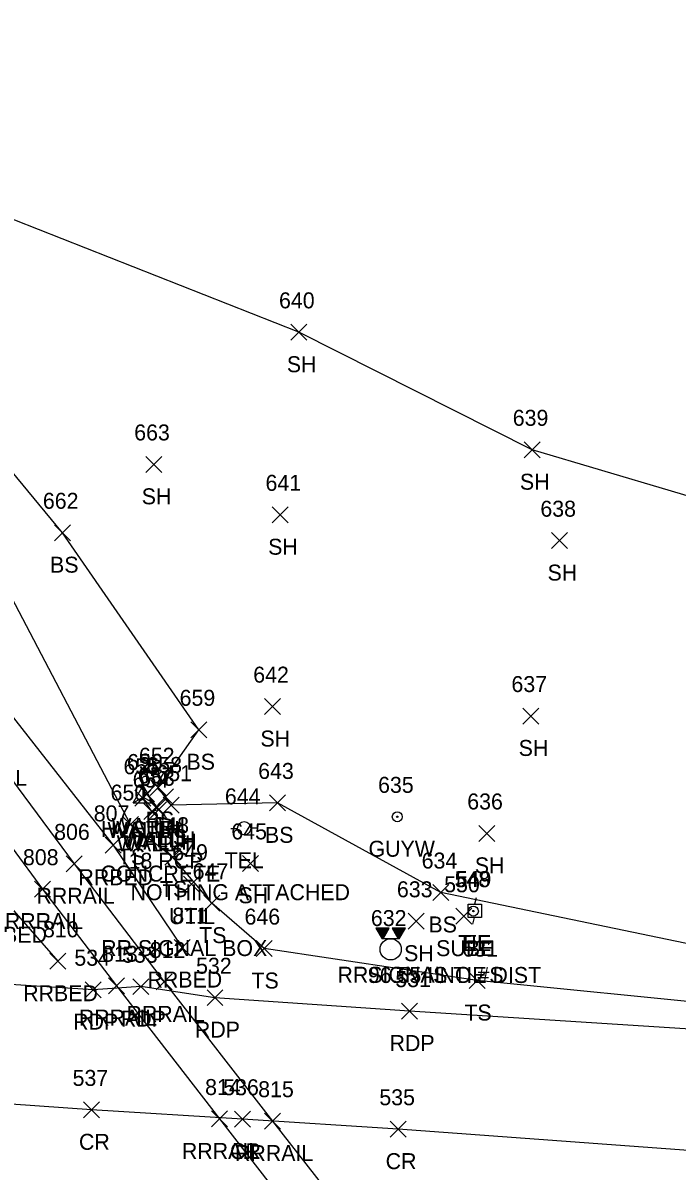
# Model space of a CAD drawing. Extents: x 1679360 to 1685861, y 903420 to 905946.
# Drawn here: x 1679800 to 1679882, y 904022.2 to 904166 of the extents above; entities that cross this region are included whole.
import ezdxf

# ---------------------------------------------------------------- set-up
doc = ezdxf.new("R2010")
doc.units = 0
for name, color, linetype in [('C_A', 7, 'Continuous'), ('C_C', 7, 'Continuous'), ('C_I', 7, 'Continuous'), ('CBP', 7, 'Continuous'), ('CPSM', 7, 'Continuous'), ('D_A', 7, 'Continuous'), ('D_C', 7, 'Continuous'), ('D_I', 7, 'Continuous'), ('D_TIC', 7, 'Continuous'), ('DHW', 7, 'Continuous'), ('L_A', 7, 'Continuous'), ('L_I', 7, 'Continuous'), ('L_TIC', 7, 'Continuous'), ('LELB', 7, 'Continuous'), ('LSOGP', 7, 'Continuous'), ('P_A', 7, 'Continuous'), ('P_I', 7, 'Continuous'), ('P_TIC', 7, 'Continuous'), ('PET', 7, 'Continuous'), ('PRC', 7, 'Continuous'), ('R_A', 7, 'Continuous'), ('R_I', 7, 'Continuous'), ('R_TIC', 7, 'Continuous'), ('RR', 7, 'Continuous'), ('RRB', 7, 'Continuous'), ('TCSH', 7, 'Continuous'), ('U_A', 7, 'Continuous'), ('U_C', 7, 'Continuous'), ('U_I', 7, 'Continuous'), ('U_TIC', 7, 'Continuous'), ('UDEFAULT', 7, 'Continuous'), ('UEPT', 7, 'Continuous'), ('UP', 7, 'Continuous'), ('UPGW', 7, 'Continuous')]:
    doc.layers.add(name, color=color, linetype=linetype)

msp = doc.modelspace()

# ---------------------------------------------------------------- linework, layer by layer
at = {"layer": 'CBP'}
for radius in [0.625, 0.0833]:
    msp.add_circle((1679856.45, 904054.75), radius, dxfattribs=at)
at = {"layer": 'CPSM'}
for p, q in [((1679813.83, 904068.31), (1679815.08, 904070.48)), ((1679816.33, 904068.31), (1679815.08, 904070.48)), ((1679815.08, 904069.03), (1679815.08, 904070.48)), ((1679813.83, 904068.31), (1679815.08, 904069.03)), ((1679815.08, 904069.03), (1679815.08, 904069.03)), ((1679815.08, 904069.03), (1679816.33, 904068.31)), ((1679813.83, 904068.31), (1679816.33, 904068.31))]:
    msp.add_line(p, q, dxfattribs=at)
at = {"layer": 'D_TIC'}
for points in [[(1679814.52, 904068.42), (1679816.52, 904070.42)], [(1679816.52, 904068.42), (1679814.52, 904070.42)], [(1679814.03, 904067.89), (1679816.03, 904069.89)], [(1679816.03, 904067.89), (1679814.03, 904069.89)], [(1679816.9, 904068.05), (1679818.9, 904070.05)], [(1679818.9, 904068.05), (1679816.9, 904070.05)], [(1679815.18, 904066.22), (1679817.18, 904068.22)], [(1679817.18, 904066.22), (1679815.18, 904068.22)], [(1679815.83, 904066.74), (1679817.83, 904068.74)], [(1679817.83, 904066.74), (1679815.83, 904068.74)], [(1679815.99, 904066.45), (1679817.99, 904068.45)], [(1679817.99, 904066.45), (1679815.99, 904068.45)]]:
    msp.add_lwpolyline(points, dxfattribs=at)
at = {"layer": 'DHW'}
msp.add_lwpolyline([(1679816.99, 904067.45), (1679816.18, 904067.22), (1679815.03, 904068.89), (1679815.52, 904069.42), (1679816.83, 904067.74)], dxfattribs=at)
at = {"layer": 'L_TIC'}
for points in [[(1679833.59, 904126.23), (1679835.59, 904128.23)], [(1679835.59, 904126.23), (1679833.59, 904128.23)], [(1679862.8, 904111.52), (1679864.8, 904113.52)], [(1679864.8, 904111.52), (1679862.8, 904113.52)], [(1679815.42, 904109.69), (1679817.42, 904111.69)], [(1679817.42, 904109.69), (1679815.42, 904111.69)], [(1679831.25, 904103.38), (1679833.25, 904105.38)], [(1679833.25, 904103.38), (1679831.25, 904105.38)], [(1679803.98, 904101.13), (1679805.98, 904103.13)], [(1679805.98, 904101.13), (1679803.98, 904103.13)], [(1679866.25, 904100.14), (1679868.25, 904102.14)], [(1679868.25, 904100.14), (1679866.25, 904102.14)], [(1679830.28, 904079.36), (1679832.28, 904081.36)], [(1679832.28, 904079.36), (1679830.28, 904081.36)], [(1679862.63, 904078.18), (1679864.63, 904080.18)], [(1679864.63, 904078.18), (1679862.63, 904080.18)], [(1679821.07, 904076.46), (1679823.07, 904078.46)], [(1679823.07, 904076.46), (1679821.07, 904078.46)], [(1679815.96, 904069.21), (1679817.96, 904071.21)], [(1679817.96, 904069.21), (1679815.96, 904071.21)], [(1679817.58, 904067.02), (1679819.58, 904069.02)], [(1679819.58, 904067.02), (1679817.58, 904069.02)], [(1679830.9, 904067.3), (1679832.9, 904069.3)], [(1679832.9, 904067.3), (1679830.9, 904069.3)], [(1679812.5, 904064.59), (1679814.5, 904066.59)], [(1679814.5, 904064.59), (1679812.5, 904066.59)], [(1679857.14, 904063.48), (1679859.14, 904065.48)], [(1679859.14, 904063.48), (1679857.14, 904065.48)], [(1679817.78, 904060.51), (1679819.78, 904062.51)], [(1679819.78, 904060.51), (1679817.78, 904062.51)], [(1679827.54, 904059.73), (1679829.54, 904061.73)], [(1679829.54, 904059.73), (1679827.54, 904061.73)], [(1679851.38, 904056.08), (1679853.38, 904058.08)], [(1679853.38, 904056.08), (1679851.38, 904058.08)], [(1679822.69, 904054.74), (1679824.69, 904056.74)], [(1679824.69, 904054.74), (1679822.69, 904056.74)], [(1679848.28, 904052.48), (1679850.28, 904054.48)], [(1679850.28, 904052.48), (1679848.28, 904054.48)], [(1679829.24, 904049.06), (1679831.24, 904051.06)], [(1679831.24, 904049.06), (1679829.24, 904051.06)], [(1679855.91, 904045.05), (1679857.91, 904047.05)], [(1679857.91, 904045.05), (1679855.91, 904047.05)]]:
    msp.add_lwpolyline(points, dxfattribs=at)
at = {"layer": 'LELB'}
for points in [[(1679970.75, 904094.89), (1679956.12, 904082.48), (1679948.06, 904070.86), (1679945.89, 904046.82), (1679943.29, 904045.3), (1679931.1, 904045.75), (1679888.37, 904049.6), (1679852.38, 904057.08), (1679831.9, 904068.3), (1679818.58, 904068.02), (1679816.96, 904070.21), (1679822.07, 904077.46), (1679804.98, 904102.13), (1679779.08, 904133.42), (1679752.11, 904167.54), (1679728.27, 904203.83), (1679707.73, 904230.55), (1679684.13, 904262.03), (1679660.64, 904296.32), (1679637.49, 904331)], [(1679957.35, 904067.57), (1679950.7, 904052.36), (1679948.48, 904046.41), (1679946.09, 904041.57), (1679931.01, 904039.98), (1679888.72, 904042.9), (1679856.91, 904046.05), (1679830.24, 904050.06), (1679823.69, 904055.74), (1679818.78, 904061.51), (1679813.5, 904065.59), (1679796.72, 904097.55), (1679771.59, 904129.9), (1679746.93, 904164.44), (1679719.12, 904199.21), (1679701.21, 904226.94), (1679680.19, 904259.65), (1679656.34, 904293.81), (1679636.23, 904329.88)]]:
    msp.add_lwpolyline(points, dxfattribs=at)
at = {"layer": 'LSOGP'}
msp.add_lwpolyline([(1680125.11, 904075.81), (1680085.61, 904079.91), (1680037.11, 904084.02), (1680000.55, 904088.21), (1679990.54, 904090.48), (1679979.64, 904095.26), (1679970.75, 904094.89), (1679938.33, 904102.77), (1679898.72, 904102.15), (1679863.8, 904112.52), (1679834.59, 904127.23), (1679795.98, 904142.46), (1679772.54, 904184.21)], dxfattribs=at)
at = {"layer": 'P_TIC'}
for points in [[(1679807.83, 904043.91), (1679809.83, 904045.91)], [(1679809.83, 904043.91), (1679807.83, 904045.91)], [(1679813.8, 904044.29), (1679815.8, 904046.29)], [(1679815.8, 904044.29), (1679813.8, 904046.29)], [(1679823.08, 904042.91), (1679825.08, 904044.91)], [(1679825.08, 904042.91), (1679823.08, 904044.91)], [(1679847.46, 904041.23), (1679849.46, 904043.23)], [(1679849.46, 904041.23), (1679847.46, 904043.23)], [(1679807.61, 904028.86), (1679809.61, 904030.86)], [(1679809.61, 904028.86), (1679807.61, 904030.86)], [(1679826.53, 904027.69), (1679828.53, 904029.69)], [(1679828.53, 904027.69), (1679826.53, 904029.69)], [(1679846.03, 904026.44), (1679848.03, 904028.44)], [(1679848.03, 904026.44), (1679846.03, 904028.44)]]:
    msp.add_lwpolyline(points, dxfattribs=at)
at = {"layer": 'PET'}
msp.add_lwpolyline([(1680210.84, 904017.73), (1680154.55, 904022.58), (1680102.27, 904026.43), (1680051.74, 904029.42), (1680001.13, 904032.43), (1679941.04, 904036.26), (1679894.06, 904039.28), (1679848.46, 904042.23), (1679824.08, 904043.91), (1679814.8, 904045.29), (1679808.83, 904044.91), (1679764.15, 904047.76), (1679716.13, 904050.9), (1679671, 904053.69), (1679626.09, 904056.57), (1679579.85, 904059.36), (1679535.31, 904061.44), (1679496.62, 904064.3), (1679468.44, 904066.43)], dxfattribs=at)
at = {"layer": 'PRC'}
msp.add_lwpolyline([(1680209.65, 904002.04), (1680152.97, 904005.78), (1680100.29, 904009.57), (1680049.21, 904012.91), (1679999.46, 904016.39), (1679940.5, 904020.99), (1679893.64, 904024.04), (1679847.03, 904027.44), (1679827.53, 904028.69), (1679808.61, 904029.86), (1679757.07, 904033.5), (1679707.39, 904036.98), (1679666.22, 904040.39), (1679623.03, 904043.25), (1679581.59, 904046.25), (1679534.87, 904049.67), (1679494.87, 904052.55), (1679467.34, 904054.68)], dxfattribs=at)
at = {"layer": 'R_TIC'}
for points in [[(1679810.33, 904061.99), (1679812.33, 904063.99)], [(1679812.33, 904061.99), (1679810.33, 904063.99)], [(1679805.42, 904059.67), (1679807.42, 904061.67)], [(1679807.42, 904059.67), (1679805.42, 904061.67)], [(1679801.46, 904056.5), (1679803.46, 904058.5)], [(1679803.46, 904056.5), (1679801.46, 904058.5)], [(1679818.97, 904049.18), (1679820.97, 904051.18)], [(1679820.97, 904049.18), (1679818.97, 904051.18)], [(1679803.41, 904047.47), (1679805.41, 904049.47)], [(1679805.41, 904047.47), (1679803.41, 904049.47)], [(1679810.73, 904044.41), (1679812.73, 904046.41)], [(1679812.73, 904044.41), (1679810.73, 904046.41)], [(1679816.7, 904044.88), (1679818.7, 904046.88)], [(1679818.7, 904044.88), (1679816.7, 904046.88)], [(1679823.64, 904027.72), (1679825.64, 904029.72)], [(1679825.64, 904027.72), (1679823.64, 904029.72)], [(1679830.29, 904027.45), (1679832.29, 904029.45)], [(1679832.29, 904027.45), (1679830.29, 904029.45)]]:
    msp.add_lwpolyline(points, dxfattribs=at)
at = {"layer": 'RR'}
for points in [[(1679726.81, 904174.45), (1679738.46, 904156.9), (1679751.84, 904137.33), (1679761.54, 904123.21), (1679774.27, 904104.96), (1679784.87, 904090.08), (1679795.44, 904075.44), (1679806.42, 904060.67), (1679817.7, 904045.88), (1679831.29, 904028.45), (1679844.1, 904012.06)], [(1679722.86, 904171.49), (1679733.8, 904154.92), (1679747.61, 904134.64), (1679756.68, 904121.56), (1679770.36, 904101.93), (1679779.96, 904088.31), (1679791.05, 904073.02), (1679802.46, 904057.5), (1679811.73, 904045.41), (1679824.64, 904028.72), (1679837.34, 904012.39)]]:
    msp.add_lwpolyline(points, dxfattribs=at)
at = {"layer": 'RRB'}
for points in [[(1679633.2, 904329.89), (1679656.09, 904293.31), (1679676.78, 904259.06), (1679698.16, 904224.73), (1679716.55, 904197.16), (1679742.3, 904159.89), (1679765.39, 904125.58), (1679788.39, 904092.22), (1679811.33, 904062.99), (1679819.97, 904050.18)], [(1679622.51, 904322.69), (1679644.95, 904286.47), (1679665.07, 904252.34), (1679687.42, 904219.26), (1679705.66, 904190.77), (1679730.04, 904152.75), (1679754.13, 904119.39), (1679776.83, 904086.3), (1679798.02, 904055.8), (1679804.41, 904048.47)]]:
    msp.add_lwpolyline(points, dxfattribs=at)
at = {"layer": 'TCSH'}
for p, q in [((1679845.91, 904052.63), (1679844.24, 904052.63)), ((1679844.24, 904052.63), (1679845.01, 904051.29)), ((1679845.14, 904051.29), (1679845.91, 904052.63)), ((1679847.94, 904052.63), (1679846.27, 904052.63)), ((1679846.27, 904052.63), (1679847.04, 904051.29)), ((1679847.17, 904051.29), (1679847.94, 904052.63)), ((1679847.17, 904051.29), (1679845.01, 904051.29)), ((1679846.09, 904049.96), (1679846.09, 904049.96))]:
    msp.add_line(p, q, dxfattribs=at)
for points in [[(1679844.28, 904052.55), (1679845.86, 904052.55)], [(1679844.36, 904052.42), (1679845.79, 904052.42)], [(1679844.44, 904052.28), (1679845.71, 904052.28)], [(1679844.51, 904052.15), (1679845.63, 904052.15)], [(1679844.59, 904052.02), (1679845.55, 904052.02)], [(1679844.67, 904051.88), (1679845.48, 904051.88)], [(1679844.75, 904051.75), (1679845.4, 904051.75)], [(1679844.82, 904051.62), (1679845.32, 904051.62)], [(1679846.3, 904052.58), (1679847.91, 904052.58)], [(1679846.38, 904052.45), (1679847.84, 904052.45)], [(1679846.46, 904052.31), (1679847.76, 904052.31)], [(1679846.53, 904052.18), (1679847.68, 904052.18)], [(1679846.61, 904052.05), (1679847.61, 904052.05)], [(1679846.69, 904051.91), (1679847.53, 904051.91)], [(1679846.76, 904051.78), (1679847.45, 904051.78)], [(1679846.84, 904051.65), (1679847.37, 904051.65)], [(1679844.9, 904051.48), (1679845.25, 904051.48)], [(1679844.98, 904051.35), (1679845.17, 904051.35)], [(1679846.92, 904051.51), (1679847.3, 904051.51)], [(1679847, 904051.38), (1679847.22, 904051.38)]]:
    msp.add_lwpolyline(points, dxfattribs=at)
msp.add_circle((1679846.09, 904049.96), 1.33, dxfattribs=at)
at = {"layer": 'U_TIC'}
for points in [[(1679854.24, 904053.11), (1679856.24, 904055.11)], [(1679856.24, 904053.11), (1679854.24, 904055.11)]]:
    msp.add_lwpolyline(points, dxfattribs=at)
at = {"layer": 'UDEFAULT'}
for points in [[(1679820.15, 904057.12), (1679822.15, 904059.12)], [(1679822.15, 904057.12), (1679820.15, 904059.12)]]:
    msp.add_lwpolyline(points, dxfattribs=at)
at = {"layer": 'UEPT'}
for p, q in [((1679856.78, 904056.43), (1679856.61, 904055.6)), ((1679855.78, 904053.93), (1679855.78, 904055.6)), ((1679855.78, 904055.6), (1679857.45, 904055.6)), ((1679856.61, 904054.76), (1679856.61, 904054.76)), ((1679857.45, 904055.6), (1679857.45, 904053.93)), ((1679857.45, 904053.93), (1679855.78, 904053.93)), ((1679856.36, 904053.1), (1679856.61, 904053.93))]:
    msp.add_line(p, q, dxfattribs=at)
at = {"layer": 'UP'}
for p, q in [((1679826.07, 904065.11), (1679826.9, 904065.11)), ((1679827.73, 904065.12), (1679827.73, 904065.12)), ((1679829.4, 904065.12), (1679828.56, 904065.12)), ((1679828.56, 904065.12), (1679828.56, 904065.12)), ((1679829.4, 904065.12), (1679829.4, 904065.12))]:
    msp.add_line(p, q, dxfattribs=at)
msp.add_circle((1679827.73, 904065.12), 0.833, dxfattribs=at)
at = {"layer": 'UPGW'}
for radius in [0.625, 0.0833]:
    msp.add_circle((1679846.92, 904066.56), radius, dxfattribs=at)

# ---------------------------------------------------------------- texts
at = {"layer": 'C_A'}
for s, p in [('HVCTRL', (1679809.78, 904064.03)), ('TIE', (1679854.53, 904049.75))]:
    msp.add_text(s, height=2, dxfattribs=at).set_placement(p)
at = {"layer": 'C_C'}
msp.add_text('96.55 IS TIE DIST', height=2, dxfattribs=at).set_placement((1679843.23, 904045.75))
at = {"layer": 'C_I'}
for s, p in [('2', (1679814.52, 904072.03)), ('548', (1679854.09, 904057.75))]:
    msp.add_text(s, height=2, dxfattribs=at).set_placement(p)
at = {"layer": 'D_A'}
for s, p in [('WALLH', (1679811.11, 904064.42)), ('P', (1679817.28, 904064.05)), ('WALLH', (1679810.62, 904063.89)), ('WALLH', (1679812.42, 904062.74)), ('WALLH', (1679811.77, 904062.22)), ('WALLH', (1679812.58, 904062.45))]:
    msp.add_text(s, height=2, dxfattribs=at).set_placement(p)
at = {"layer": 'D_C'}
for s, p in [('18 RCP', (1679813.26, 904060.05)), ('CONCRETE', (1679809.74, 904058.45))]:
    msp.add_text(s, height=2, dxfattribs=at).set_placement(p)
at = {"layer": 'D_I'}
for s, p in [('655', (1679812.62, 904071.89)), ('656', (1679813.06, 904072.42)), ('658', (1679815.49, 904072.05)), ('654', (1679813.77, 904070.22)), ('657', (1679814.42, 904070.74)), ('653', (1679814.58, 904070.45))]:
    msp.add_text(s, height=2, dxfattribs=at).set_placement(p)
at = {"layer": 'L_A'}
for s, p in [('SH', (1679833.08, 904122.23)), ('SH', (1679862.28, 904107.52)), ('SH', (1679814.9, 904105.69)), ('SH', (1679830.74, 904099.38)), ('BS', (1679803.42, 904097.13)), ('SH', (1679865.74, 904096.14)), ('SH', (1679829.77, 904075.36)), ('SH', (1679862.12, 904074.18)), ('BS', (1679820.51, 904072.46)), ('BS', (1679815.4, 904065.21)), ('BS', (1679817.02, 904063.02)), ('BS', (1679830.34, 904063.3)), ('TS', (1679811.91, 904060.59)), ('SH', (1679856.63, 904059.48)), ('TS', (1679817.19, 904056.51)), ('SH', (1679827.03, 904055.73)), ('BS', (1679850.82, 904052.08)), ('TS', (1679822.1, 904050.74)), ('SH', (1679847.77, 904048.48)), ('TS', (1679828.65, 904045.06)), ('TS', (1679855.32, 904041.05))]:
    msp.add_text(s, height=2, dxfattribs=at).set_placement(p)
at = {"layer": 'L_I'}
for s, p in [('640', (1679832.1, 904130.23)), ('639', (1679861.38, 904115.52)), ('663', (1679813.96, 904113.69)), ('641', (1679830.41, 904107.38)), ('662', (1679802.52, 904105.13)), ('638', (1679864.84, 904104.14)), ('642', (1679828.87, 904083.36)), ('637', (1679861.22, 904082.18)), ('659', (1679819.65, 904080.46)), ('652', (1679814.55, 904073.21)), ('643', (1679829.49, 904071.3)), ('651', (1679816.74, 904071.02)), ('650', (1679811, 904068.59)), ('636', (1679855.68, 904067.48)), ('648', (1679816.37, 904064.51)), ('645', (1679826.13, 904063.73)), ('634', (1679849.97, 904060.08)), ('647', (1679821.28, 904058.74)), ('633', (1679846.87, 904056.48)), ('646', (1679827.78, 904053.06)), ('631', (1679855.06, 904049.05))]:
    msp.add_text(s, height=2, dxfattribs=at).set_placement(p)
at = {"layer": 'P_A'}
for s, p in [('RDP', (1679806.31, 904039.91)), ('RDP', (1679812.29, 904040.29)), ('RDP', (1679821.56, 904038.91)), ('RDP', (1679845.95, 904037.23)), ('CR', (1679807.04, 904024.86)), ('CR', (1679825.96, 904023.69)), ('CR', (1679845.46, 904022.44))]:
    msp.add_text(s, height=2, dxfattribs=at).set_placement(p)
at = {"layer": 'P_I'}
for s, p in [('533', (1679812.44, 904048.29)), ('534', (1679806.46, 904047.91)), ('532', (1679821.71, 904046.91)), ('531', (1679846.67, 904045.23)), ('537', (1679806.24, 904032.86)), ('536', (1679825.11, 904031.69)), ('535', (1679844.67, 904030.44))]:
    msp.add_text(s, height=2, dxfattribs=at).set_placement(p)
at = {"layer": 'R_A'}
for s, p in [('RRRAIL', (1679790.73, 904070.44)), ('RRBED', (1679806.97, 904057.99)), ('RRRAIL', (1679801.71, 904055.67)), ('RRRAIL', (1679797.75, 904052.5)), ('RRBED', (1679793.67, 904050.8)), ('RRSIGNAL', (1679839.42, 904045.78)), ('RRBED', (1679815.62, 904045.18)), ('RRBED', (1679800.05, 904043.47)), ('RRRAIL', (1679807.02, 904040.41)), ('RRRAIL', (1679812.99, 904040.88)), ('RRRAIL', (1679819.93, 904023.72)), ('RRRAIL', (1679826.58, 904023.45))]:
    msp.add_text(s, height=2, dxfattribs=at).set_placement(p)
at = {"layer": 'R_I'}
for s, p in [('807', (1679808.89, 904065.99)), ('806', (1679803.93, 904063.67)), ('808', (1679800.02, 904060.5)), ('811', (1679818.74, 904053.18)), ('632', (1679843.61, 904052.88)), ('810', (1679802.53, 904051.47)), ('813', (1679809.93, 904048.41)), ('812', (1679815.91, 904048.88)), ('814', (1679822.84, 904031.72)), ('815', (1679829.49, 904031.45))]:
    msp.add_text(s, height=2, dxfattribs=at).set_placement(p)
at = {"layer": 'U_A'}
for s, p in [('GUYW', (1679843.31, 904061.56)), ('TEL', (1679825.29, 904060.12)), ('UTIL', (1679818.31, 904053.12)), ('EL', (1679855.15, 904049.76)), ('SUBE', (1679851.78, 904049.11))]:
    msp.add_text(s, height=2, dxfattribs=at).set_placement(p)
at = {"layer": 'U_C'}
for s, p in [('NOTHING ATTACHED', (1679813.5, 904056.12)), ('RR SIGNAL BOX', (1679809.82, 904049.12)), ('NO #S', (1679852.2, 904045.76))]:
    msp.add_text(s, height=2, dxfattribs=at).set_placement(p)
at = {"layer": 'U_I'}
for s, p in [('635', (1679844.51, 904069.56)), ('644', (1679825.32, 904068.12)), ('649', (1679818.73, 904061.12)), ('550', (1679852.79, 904057.11)), ('549', (1679854.24, 904057.76))]:
    msp.add_text(s, height=2, dxfattribs=at).set_placement(p)

doc.saveas('drawing.dxf')
